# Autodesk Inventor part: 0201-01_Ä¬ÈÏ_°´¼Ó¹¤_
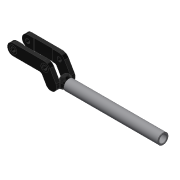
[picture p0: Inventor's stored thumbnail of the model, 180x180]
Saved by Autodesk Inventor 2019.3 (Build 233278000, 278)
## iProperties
Created: 2010-06
Part Number: 0201-01_Ä¬ÈÏ_°´¼Ó¹¤_
Material: Ogólny
Document SubType Name: Modeling
Designer: CADENGINEERING4
Density: 1 g/cm^3
Appearance: Domyślna
Author: CADENGINEERING4
Revision Number: ÈÎºÎ
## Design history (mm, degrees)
feature "NONE"
feature "NONE:1"
node "Bryła1"
node "Bryła2"
